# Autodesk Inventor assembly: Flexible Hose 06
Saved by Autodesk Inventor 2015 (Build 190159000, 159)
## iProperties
Created: 2013-02
Part Number: Flexible Hose 06
Document SubType Name: Assembly
Designer: Marci
Name: Hydraulic Hose - No Fittings
ActiveState: True
PipeType: Flexible Hose
Material: UnInitValue
Standard: UnInitValue
FittingMaterial: UnInitValue
FittingStandard: UnInitValue
RouteDirection90: UnInitValue
RouteDirection45: UnInitValue
IsFlanged: UnInitValue
IsButtWelded: UnInitValue
DiameterType: Nominal
Diameter: 1/4
Schedule: ID=0.25
OD: 1,4986
ID: 0,635
Ending: UnInitValue
IntermediateSegmentsMin: UnInitValue
IntermediateSegmentsMax: UnInitValue
IntermediateSegmentsInc: UnInitValue
TerminationSegmentsMin: UnInitValue
TerminationSegmentsMax: UnInitValue
TerminationSegmentsInc: UnInitValue
RoundUpValue: 0.125 in
DefaultBendRadius: UnInitValue
BendRadius: 0.500 in
PipingComponentColor: Blue (Flat)
PipeKey: v3#d489867e-ac9b-47ea-b952-0a1b885f66be#1
CouplingKey: UnInitValue
Elbow90Key: UnInitValue
Elbow45Key: UnInitValue
SuppressStartFitting: True
SuppressEndFitting: True
FlangeKey: UnInitValue
GasketKey: UnInitValue
Gap: UnInitValue
UseSubASM: True
_ComponentInfo: <CS><C N="Pipe" R="0,749300" OR="0,749300" IR="0,317500" PL="PL" PartType="pipe" SymKey="" PN="Parker hidraulikatömlő - No Skive 1/4"><CO N="1"><FE V="0"/><FD V
ShowGap: UnInitValue
MixedUnits: UnInitValue
UseFlangsForCouplings: UnInitValue
IsSelfDraining: UnInitValue
ElbowCustomKey: UnInitValue
Angle: UnInitValue
Author: Marci
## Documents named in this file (3)
- C:\Users\Andrew Almeida\Documents\Projeto WS2015\WS2015 CAD Data ANLAS\01\Pneumatic System\Engine\Pneumatikus hajtás\Teljes hajtás\AIP\Tube and Pipe\Run06\Teljes hajtás.Hose06.iam
- C:\Users\Andrew Almeida\Documents\Projeto WS2015\WS2015 CAD Data ANLAS\01\Pneumatic System\Engine\Pneumatikus hajtás\Teljes hajtás\AIP\Tube and Pipe\Run06\Teljes hajtás.Hose06.ipt
- C:\Users\Andrew Almeida\Documents\Projeto WS2015\WS2015 CAD Data ANLAS\01\Pneumatic System\Engine\Pneumatikus hajtás\Teljes hajtás\AIP\Tube and Pipe\Run06\pifhose.1360342989485.ipt
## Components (2 placed, 2 different names)
1. Hose06
2. Flexible Hose:1
